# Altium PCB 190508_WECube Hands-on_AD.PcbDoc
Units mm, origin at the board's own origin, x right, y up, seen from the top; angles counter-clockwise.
Board outline 87.3 x 114.68 mm, 5 copper layers (Top, Layer 2, Layer 3, Layer 4, Bottom), stack 1.05 mm thick; 0 components, 0 nets, 41 pads, 0 vias.
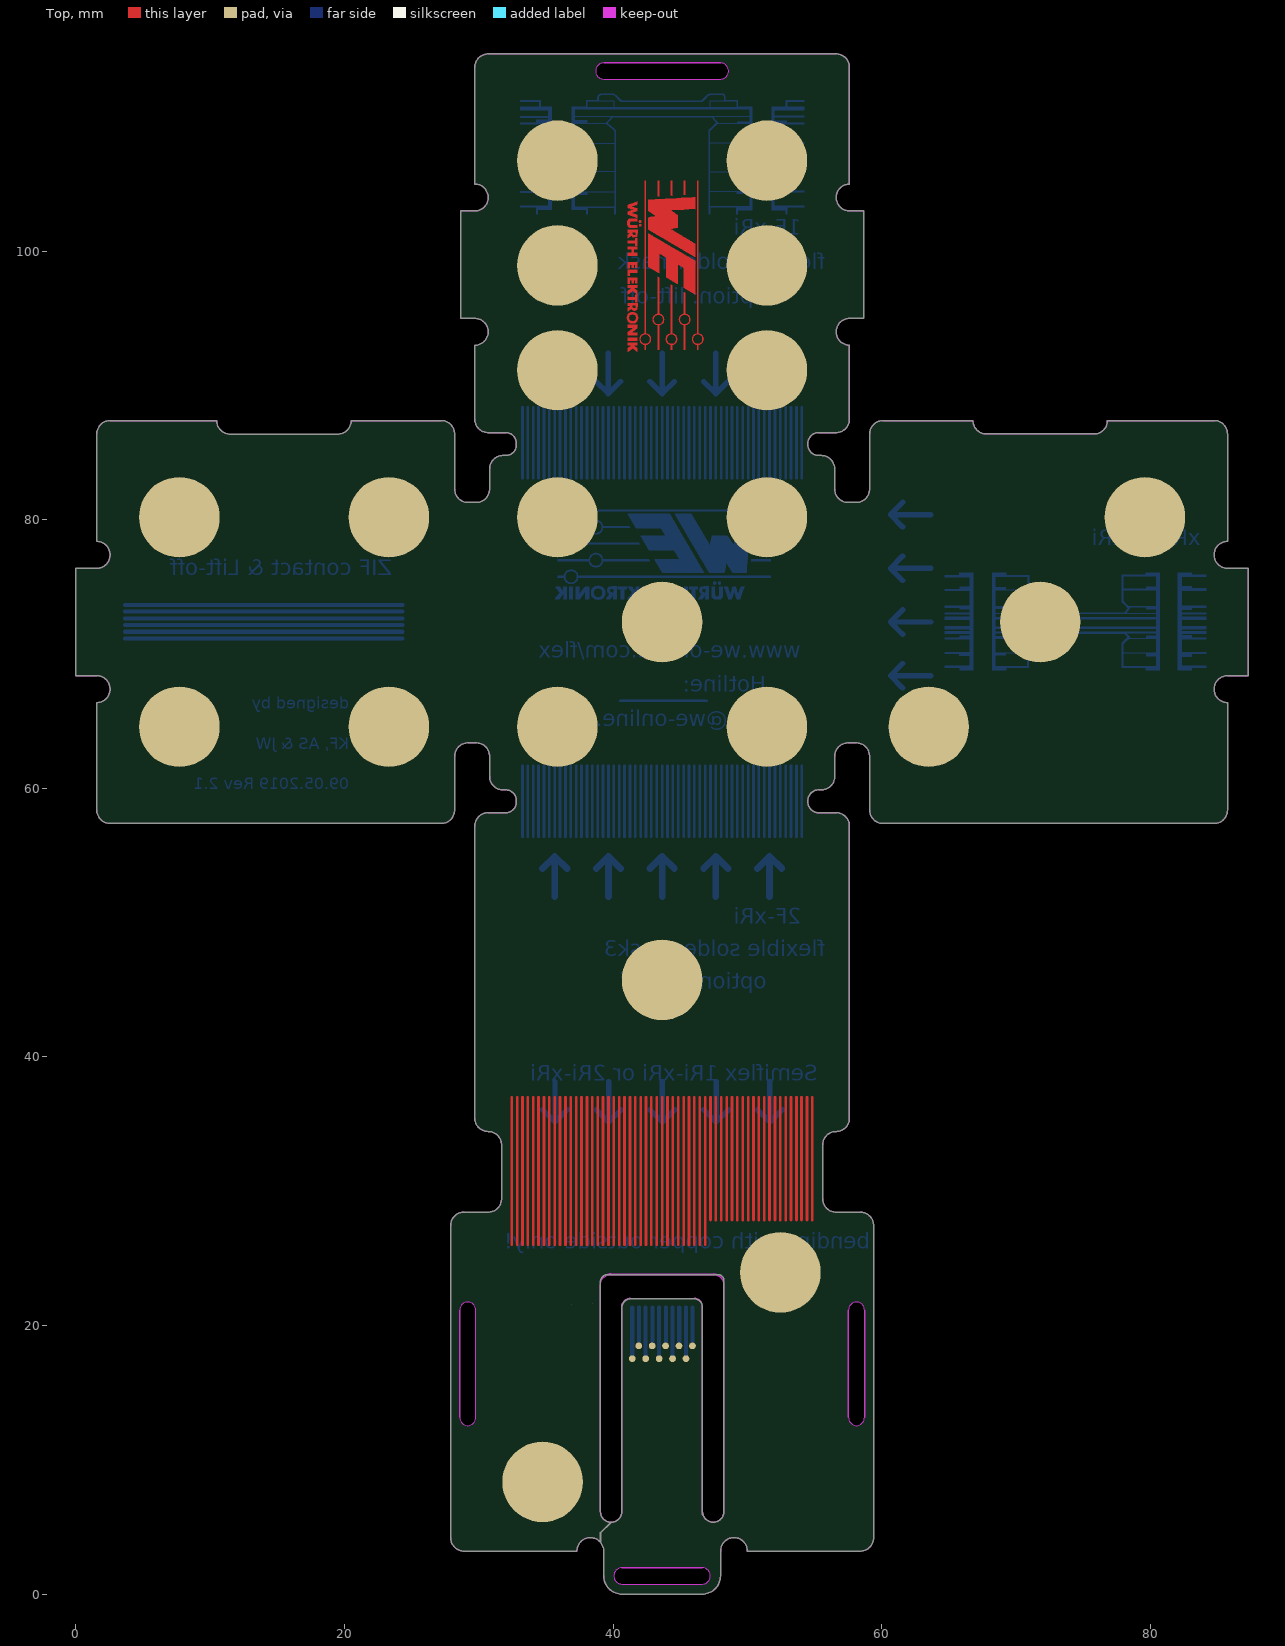
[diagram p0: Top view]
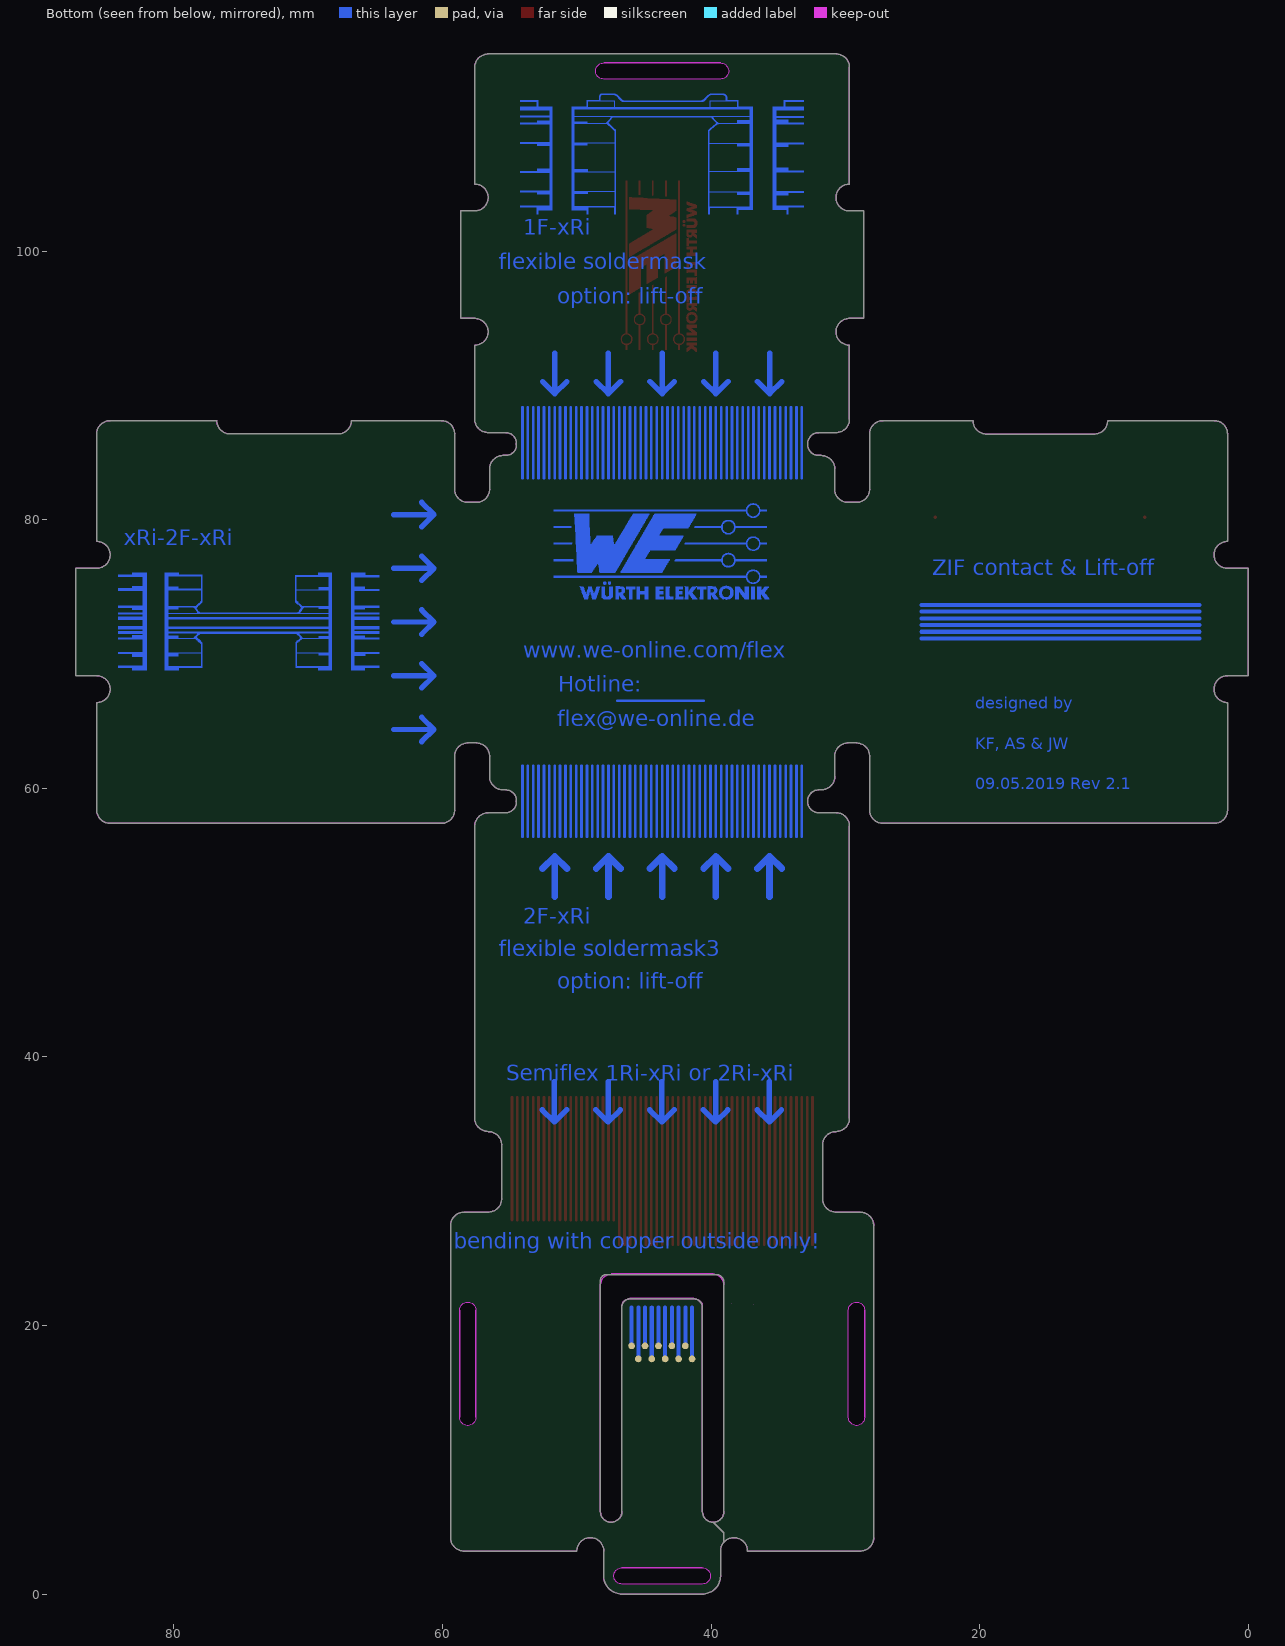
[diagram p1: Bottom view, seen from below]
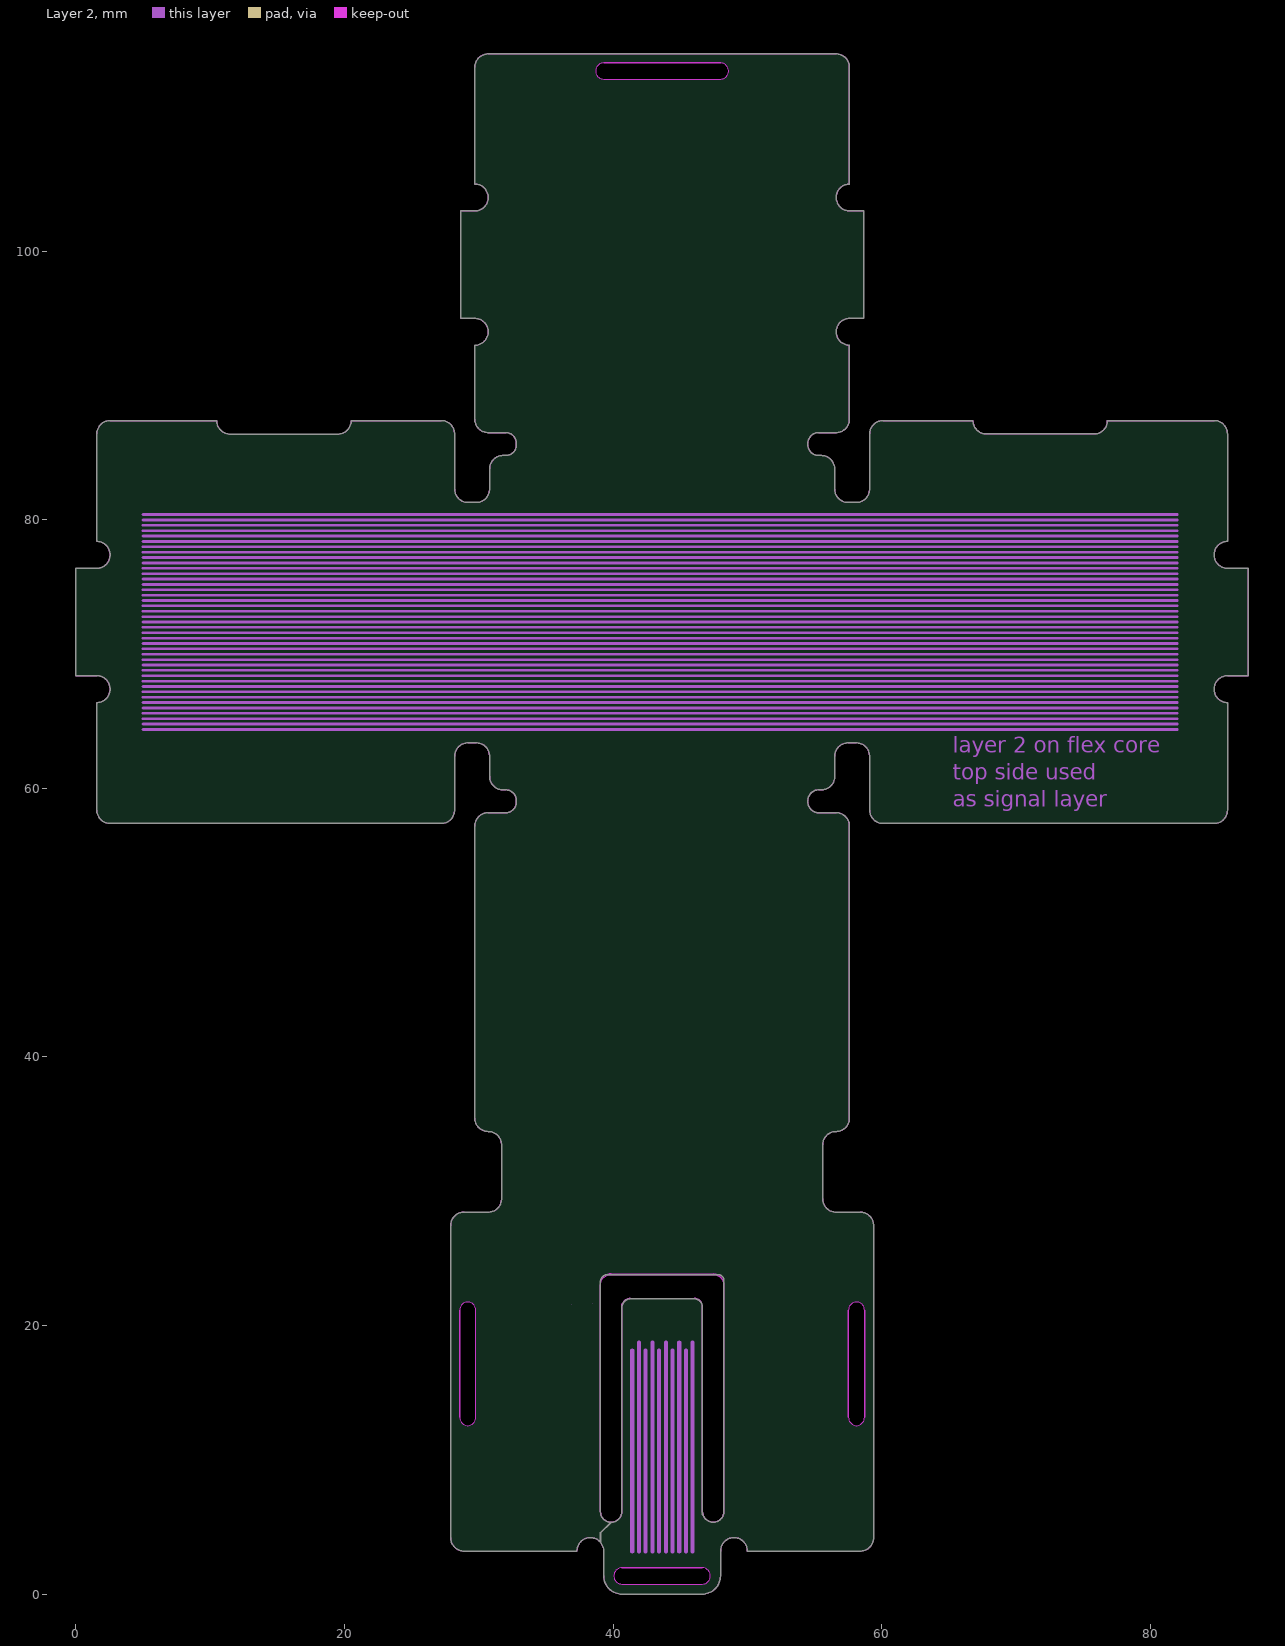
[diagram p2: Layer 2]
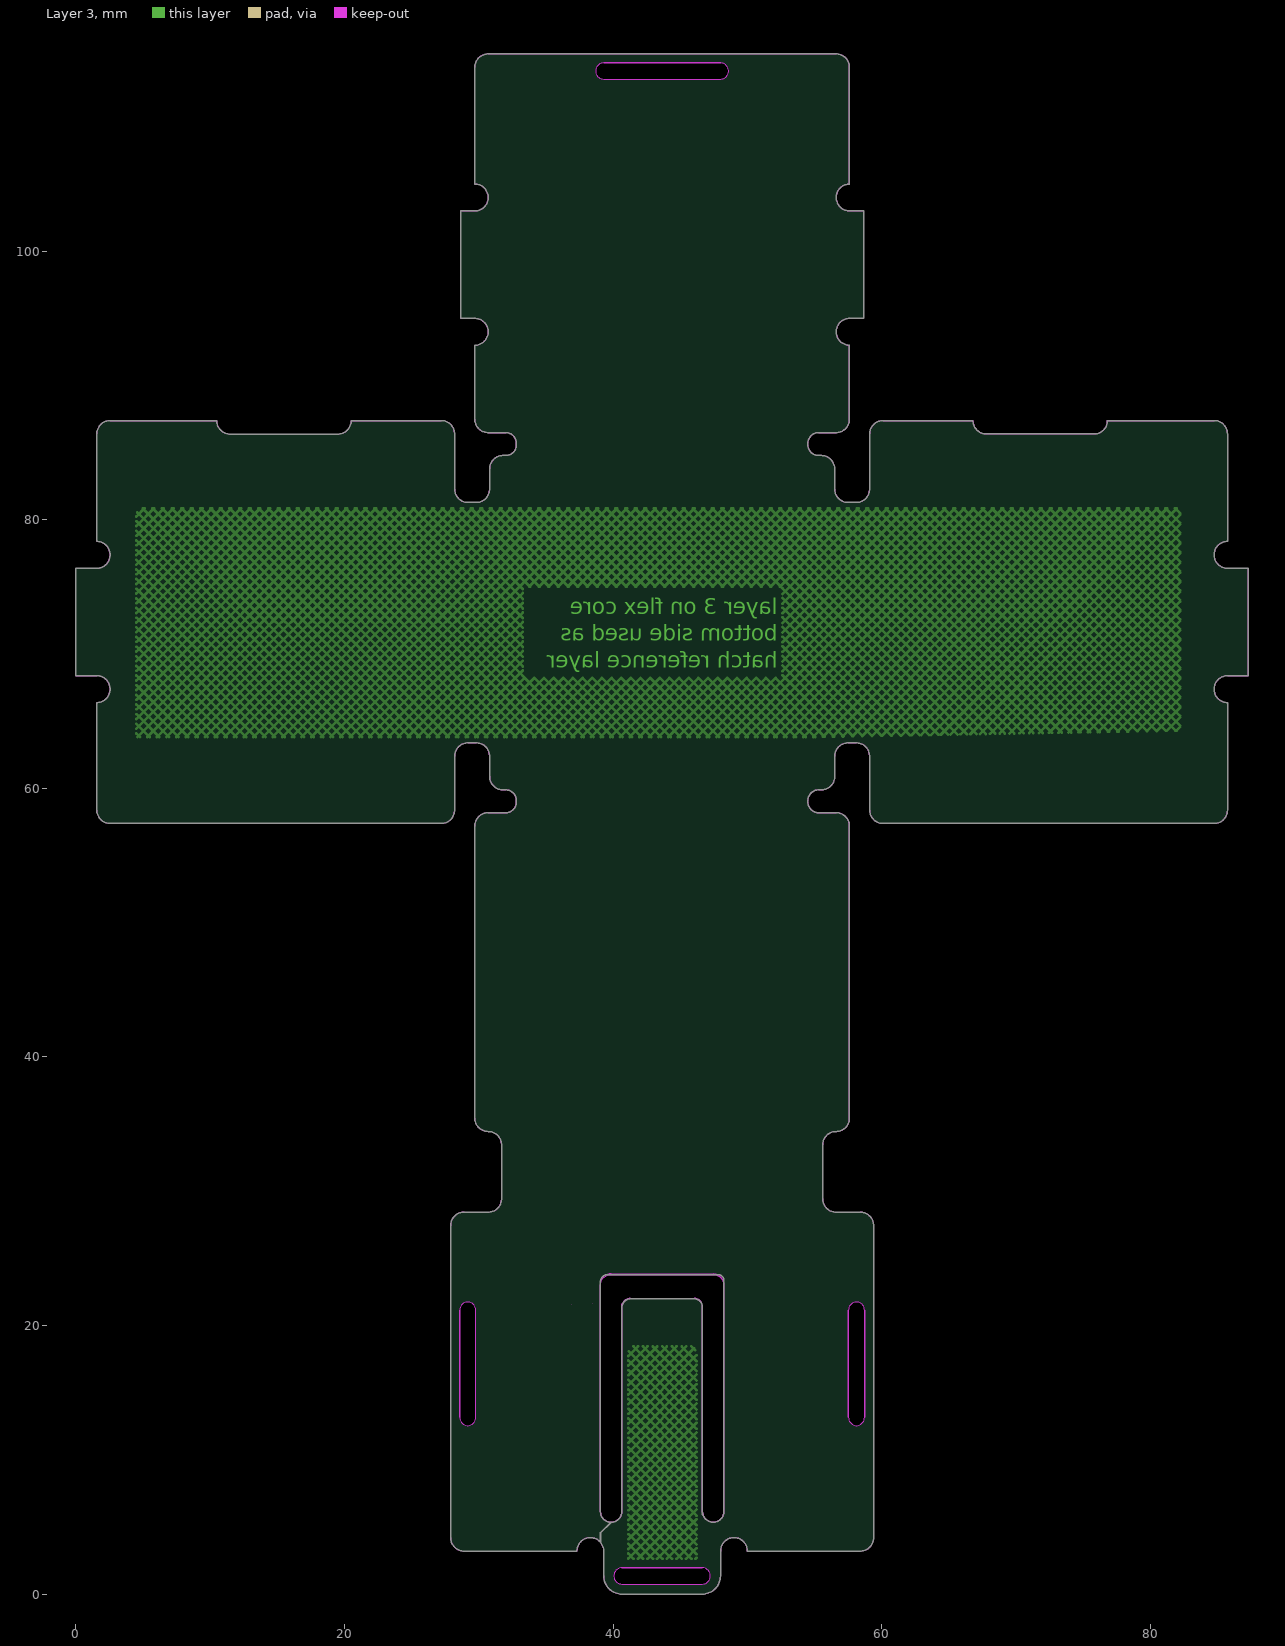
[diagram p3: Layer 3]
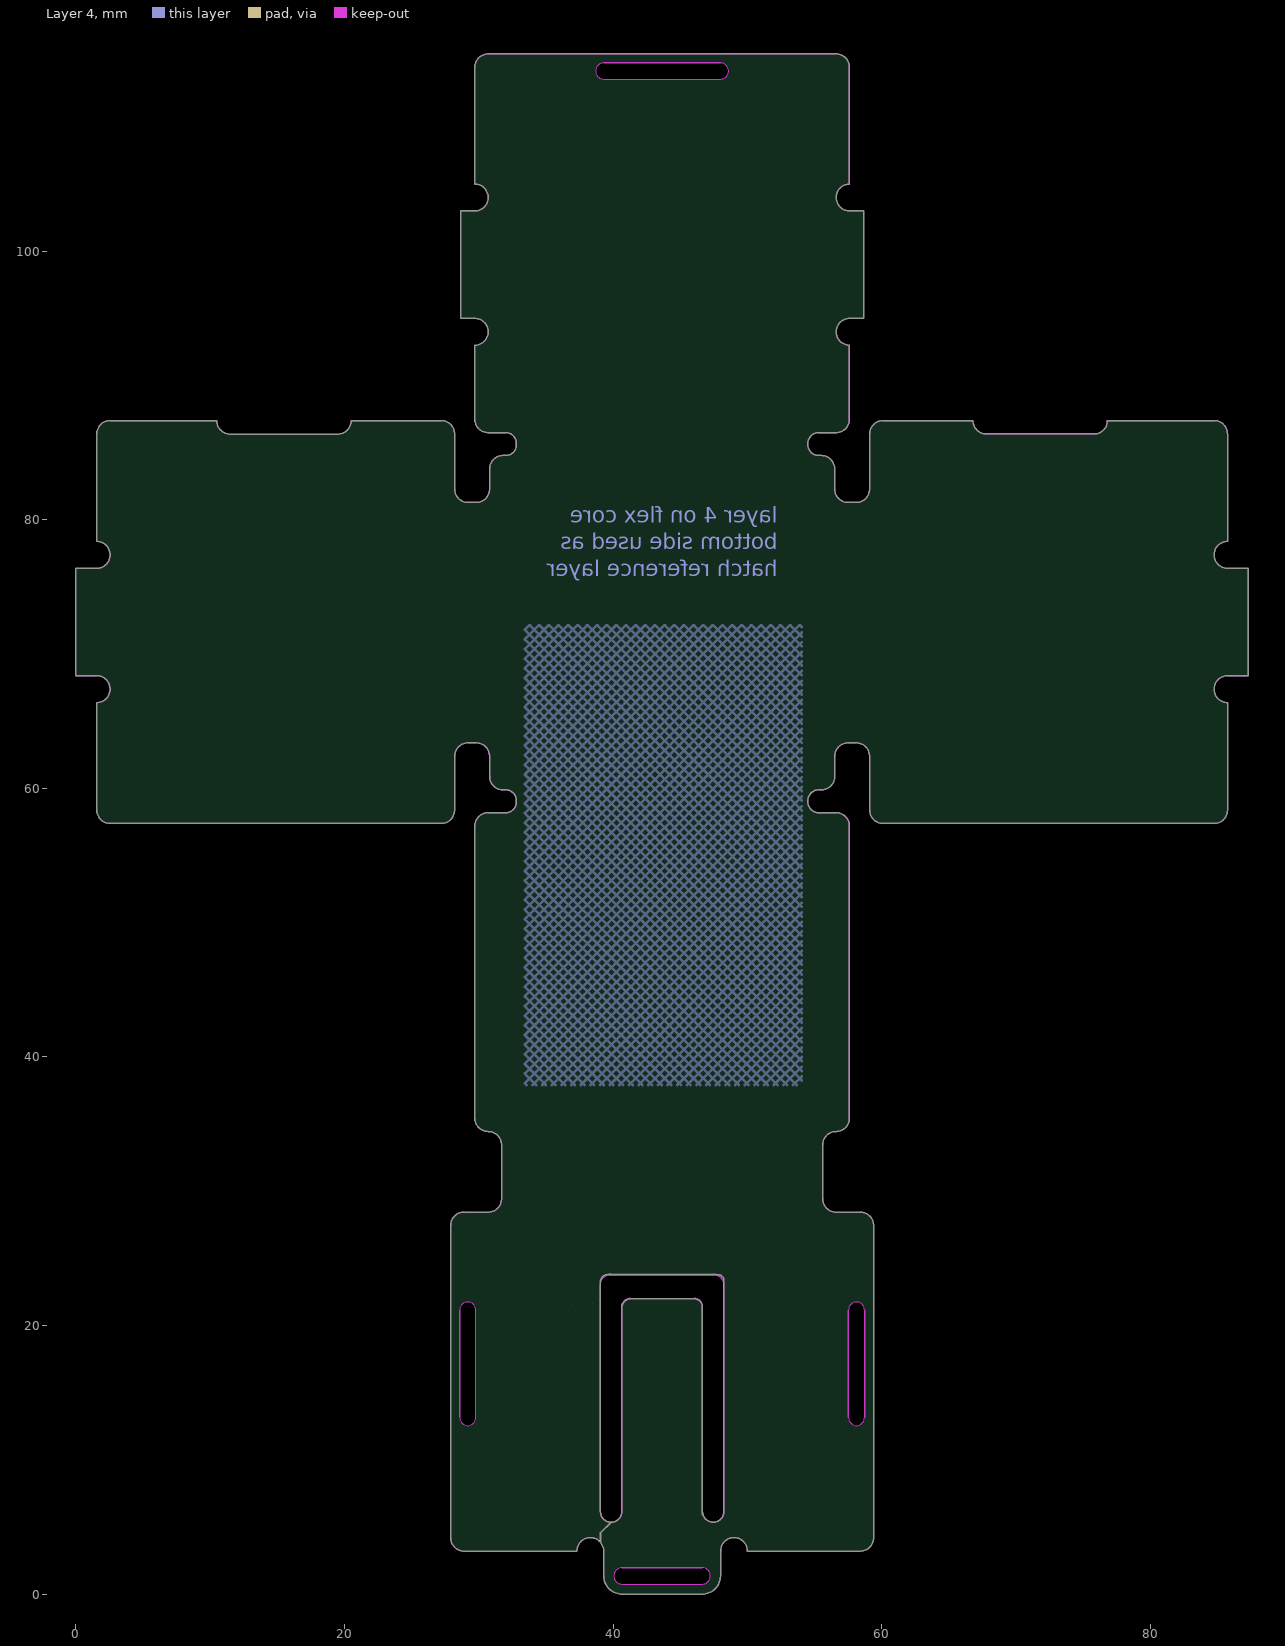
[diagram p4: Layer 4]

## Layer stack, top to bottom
Inner Top Coverlay: solder mask 0.025, Polyimide, Dk 3.6
Inner Top Coverlay: solder mask 0.015, Flexible Solder Resist, Dk 3.4
Inner Top Coverlay: solder mask 0.015, Solder Resist, Dk 3.7
Inner Top Coverlay: solder mask 0.025, Polyimide, Dk 3.6
Top: signal copper 0.04
2x1080: prepreg 0.134, FR4 TG150, Dk 4.2
FR4: core 0.2, Dk 4.2
106 LowFlow: prepreg 0.095, FR4 PP TG150, Dk 4.2
Layer 2: signal copper 0.017
Polyimide 18-50-18: core 0.05, Polyimide adhesiveless, Dk 3.6
Layer 3: signal copper 0.017
106 LowFlow: prepreg 0.095, FR4 PP TG150, Dk 4.9
FR4: core 0.2, FR4 TG150, Dk 4.9
106 LowFlow: prepreg 0.095, FR4 PP TG150, Dk 4.9
Layer 4: signal copper 0.017
Polyimide 18-50-18: core 0.05, Polyimide adhesiveless, Dk 3.6
Bottom: signal copper 0.04
Bottom Coverlay: solder mask 0.015, Polyimide, Dk 3.6
Bottom Coverlay: solder mask 0.015, Solder Resist, Dk 3.7
Bottom Coverlay: solder mask 0.015, Flexible Solder Resist, Dk 3.4
Bottom Coverlay: solder mask 0.025, Polyimide, Dk 3.6

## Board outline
27.9,4.2 ccw(c28.9,4.2) 28.9,3.2 cw(c28.9,3.2) 28.9,3.2 37.3,3.2 cw(c38.3,3.2) 39.054,3.857 39.054,4.569 cw(c39.055,4.569) 39.054,4.569 39.835,5.35 cw(c39.85,6.15) 39.049,6.15 cw(c39.05,6.15) 39.05,6.15 39.05,23.23 cw(c39.61,23.23) 39.61,23.79 47.8,23.79 cw(c47.8,23.34) 48.25,23.34 48.25,6.15 cw(c47.45,6.15) 46.65,6.113 46.65,5.923 cw(c46.65,5.923) 46.65,5.923 46.65,21.387 ccw(c46.057,21.387) 46.057,21.98 41.291,21.98 ccw(c41.291,21.339) 40.65,21.339 40.65,6.15 cw(c40.65,6.15) 40.65,6.15 cw(c39.85,6.15) 39.864,5.35 39.066,4.552 39.066,3.843 cw(c38.3,3.2) 39.3,3.2 39.3,1.35 ccw(c40.65,1.35) 40.65,0 cw(c40.65,0) 40.65,0 46.65,0 ccw(c46.65,1.35) 48,1.35 cw(c48,1.35) 48,1.35 48,3.2 cw(c49,3.2) 50,3.2 58.4,3.2 cw(c58.4,3.2) 58.4,3.2 ccw(c58.4,4.2) 59.4,4.2 59.4,27.44 ccw(c58.4,27.44) 58.4,28.44 56.6,28.44 cw(c56.6,29.44) 55.6,29.44 55.6,33.44 cw(c56.6,33.44) 56.6,34.44 ccw(c56.6,35.44) 57.6,35.44 57.6,57.18 cw(c57.6,57.18) 57.6,57.18 cw(c56.6,57.18) 57.6,57.18 ccw(c56.6,57.18) 56.6,58.18 55.3,58.18 cw(c55.3,58.98) 54.5,58.98 54.5,59.08 cw(c55.3,59.08) 55.3,59.88 55.5,59.88 ccw(c55.5,60.88) 56.5,60.88 56.5,62.38 ccw(c56.5,62.38) 56.5,62.38 cw(c57.5,62.38) 57.5,63.38 58.1,63.38 cw(c58.1,62.38) 59.1,62.38 59.1,58.38 ccw(c59.1,58.38) 59.1,58.38 ccw(c60.1,58.38) 60.1,57.38 84.75,57.38 ccw(c84.75,58.38) 85.75,58.38 cw(c85.75,58.38) 85.75,58.38 85.75,66.38 cw(c85.75,67.38) 85.75,68.38 87.3,68.38 87.3,76.38 85.75,76.38 cw(c85.75,77.38) 85.75,78.38 85.75,86.38 ccw(c84.75,86.38) 84.75,87.38 76.81,87.38 cw(c75.8,87.39) 75.8,86.38 cw(c75.8,87.39) 75.8,86.38 ccw(c75.8,86.38) 75.8,86.38 67.8,86.38 cw(c67.8,86.38) 67.8,86.38 cw(c67.8,87.39) 66.79,87.38 60.1,87.38 cw(c60.1,87.38) 60.1,87.38 cw(c60.1,86.38) 60.1,87.38 ccw(c60.1,86.38) 59.1,86.38 cw(c59.1,86.38) 59.1,86.38 59.1,82.28 cw(c58.1,82.28) 58.1,81.28 57.5,81.28 cw(c57.5,82.28) 56.5,82.28 56.5,83.78 cw(c56.5,83.78) 56.5,83.78 cw(c55.5,83.78) 56.5,83.78 ccw(c55.5,83.78) 55.5,84.78 cw(c55.5,84.78) 55.5,84.78 55.3,84.78 cw(c55.3,85.58) 54.5,85.58 54.5,85.68 cw(c55.3,85.68) 55.3,86.48 56.6,86.48 ccw(c56.6,87.48) 57.6,87.48 57.6,92.99 cw(c57.61,93.99) 57.61,94.99 58.66,94.99 58.66,102.99 57.61,102.99 cw(c57.61,103.99) 57.6,104.99 57.6,113.68 ccw(c56.6,113.68) 56.6,114.68 30.7,114.68 ccw(c30.7,113.68) 29.7,113.68 29.7,104.99 cw(c29.7,103.99) 30.7,103.99 cw(c29.7,103.99) 29.7,102.99 28.65,102.99 28.65,94.99 29.7,94.99 cw(c29.7,93.99) 30.7,93.99 cw(c29.7,93.99) 29.7,92.99 29.7,87.48 ccw(c30.7,87.48) 30.7,86.48 32,86.48 cw(c32,85.68) 32.8,85.68 32.8,85.58 cw(c32,85.58) 32,84.78 31.8,84.78 ccw(c31.8,84.78) 31.8,84.78 ccw(c31.8,83.78) 30.8,83.78 30.8,82.28 cw(c29.8,82.28) 29.8,81.28 29.2,81.28 cw(c29.2,82.28) 28.2,82.28 28.2,86.38 ccw(c27.2,86.38) 27.2,87.38 20.5,87.38 cw(c19.49,87.38) 19.49,86.37 cw(c19.49,87.38) 19.49,86.37 11.49,86.37 cw(c11.49,86.37) 11.49,86.37 cw(c11.49,87.38) 10.48,87.38 2.55,87.38 cw(c2.55,87.38) 2.55,87.38 cw(c2.55,86.38) 2.55,87.38 ccw(c2.55,86.38) 1.55,86.38 1.55,78.38 cw(c1.55,77.38) 2.55,77.38 cw(c1.55,77.38) 1.55,76.38 0,76.38 0,68.38 1.55,68.38 cw(c1.55,67.38) 2.55,67.38 cw(c1.55,67.38) 1.55,66.38 1.55,58.38 cw(c1.55,58.38) 1.55,58.38 cw(c2.55,58.38) 1.55,58.38 ccw(c2.55,58.38) 2.55,57.38 cw(c2.55,57.38) 2.55,57.38 27.2,57.38 ccw(c27.2,58.38) 28.2,58.38 28.2,62.38 cw(c29.2,62.38) 29.2,63.38 29.8,63.38 cw(c29.8,62.38) 30.8,62.38 cw(c30.8,62.38) 30.8,62.38 30.8,60.88 ccw(c31.8,60.88) 31.8,59.88 cw(c31.8,59.88) 31.8,59.88 32,59.88 cw(c32,59.08) 32.8,59.08 32.8,58.98 cw(c32,58.98) 32,58.18 30.7,58.18 ccw(c30.7,57.18) 29.7,57.18 cw(c29.7,57.18) 29.7,57.18 29.7,35.44 ccw(c30.7,35.44) 30.7,34.44 cw(c30.7,33.44) 31.7,33.44 31.7,29.44 cw(c30.7,29.44) 30.7,28.44 28.9,28.44 ccw(c28.9,27.44) 27.9,27.44
cut-out: 39.05,6.15 39.049,22.988 cw(c39.851,22.988) 39.851,23.79 47.446,23.79 cw(c47.446,22.987) 48.25,22.988 48.25,6.15 cw(c47.45,6.15) 46.65,6.15 46.65,21.339 ccw(c46.033,21.363) 46.057,21.98 41.421,21.98 ccw(c41.331,21.298) 40.65,21.387 40.65,6.15 cw(c39.85,6.15)
cut-out: 28.575,13.15 ccw(c29.175,13.15) 29.775,13.15 29.775,21.15 ccw(c29.175,21.15) 28.575,21.15
cut-out: 57.525,13.15 ccw(c58.125,13.15) 58.725,13.15 58.725,21.15 ccw(c58.125,21.15) 57.525,21.15
cut-out: 40.65,0.75 46.65,0.75 ccw(c46.65,1.35) 46.65,1.95 40.65,1.95 ccw(c40.65,1.35)
cut-out: 39.3,112.805 48,112.805 ccw(c48,113.405) 48,114.005 39.3,114.005 ccw(c39.3,113.405)
cut-out: 39.05,6.15
cut-out: 36.88,21.55
cut-out: 38.45,21.67
board region "Layer Stack Region 1": 56.202,28.527 56.31,28.483 56.502,28.444 56.6,28.44 58.4,28.44 58.498,28.44 58.692,28.401 58.873,28.326 59.037,28.216 59.176,28.077 59.286,27.913 59.361,27.732 59.4,27.538 59.4,27.44 59.4,4.2 59.4,4.102 59.361,3.908 59.286,3.727 59.176,3.563 59.037,3.424 58.874,3.314 58.692,3.239 58.498,3.2 58.4,3.2 50,3.2 49.992,3.331 49.924,3.583 49.793,3.809 49.609,3.994 49.383,4.124 49.13,4.192 48.869,4.192 48.617,4.124 48.391,3.994 48.206,3.809 48.076,3.583 48.008,3.331 48,3.2 48,1.35 48,1.217 47.948,0.956 47.846,0.711 47.698,0.49 47.51,0.302 47.289,0.154 47.044,0.052 46.783,0 46.65,0 40.65,0 40.517,0 40.256,0.052 40.011,0.154 39.79,0.302 39.602,0.49 39.454,0.711 39.352,0.956 39.3,1.217 39.3,1.35 39.3,3.2 39.297,3.287 39.266,3.459 39.207,3.623 39.12,3.774 39.066,3.843 39.066,4.552 39.864,5.35 39.941,5.355 40.093,5.387 40.235,5.449 40.247,5.457 47.161,5.404 47.165,5.402 47.365,5.354 47.571,5.359 47.769,5.416 47.946,5.522 48.09,5.669 48.191,5.848 48.244,6.047 48.25,6.15 48.25,23.34 48.242,23.428 48.175,23.59 48.05,23.715 47.888,23.782 47.8,23.79 39.61,23.79 39.501,23.78 39.299,23.696 39.144,23.541 39.06,23.339 39.05,23.23 39.05,6.15 39.053,6.072 39.083,5.92 39.141,5.777 39.227,5.647 39.335,5.537 39.463,5.449 39.606,5.388 39.757,5.355 39.835,5.35 39.054,4.569 39.054,3.857 38.946,3.963 38.689,4.122 38.396,4.196 38.095,4.179 37.812,4.073 37.574,3.888 37.401,3.64 37.311,3.351 37.3,3.2 28.9,3.2 28.802,3.2 28.608,3.239 28.426,3.314 28.263,3.424 28.124,3.563 28.014,3.727 27.939,3.908 27.9,4.102 27.9,4.2 27.9,27.44 27.9,27.538 27.939,27.732 28.014,27.913 28.124,28.077 28.263,28.216 28.427,28.326 28.608,28.401 28.802,28.44 28.9,28.44 30.7,28.44 30.798,28.444 30.99,28.483 31.116,28.535
board region "Layer Stack Region 1": 46.65,16.75 46.65,5.929 46.65,6.113 46.662,6.01 46.724,5.814 46.833,5.64 46.984,5.499 47.161,5.404 40.247,5.457 40.363,5.536 40.472,5.647 40.557,5.776 40.616,5.92 40.646,6.072 40.65,6.15 40.65,16.755
board region "Layer Stack Region 1": 46.65,19.188 46.65,16.75 40.65,16.755 40.65,19.197
board region "Layer Stack Region 1": 56.947,34.502 56.892,34.479 56.698,34.44 56.6,34.44 56.502,34.436 56.31,34.397 56.128,34.322 55.965,34.213 55.827,34.075 55.718,33.912 55.643,33.73 55.604,33.538 55.6,33.44 55.6,29.44 55.604,29.342 55.643,29.15 55.718,28.968 55.827,28.805 55.965,28.667 56.128,28.558 56.202,28.527 31.116,28.535 31.172,28.558 31.335,28.667 31.473,28.805 31.582,28.968 31.657,29.15 31.696,29.342 31.7,29.44 31.7,33.44 31.696,33.538 31.657,33.73 31.582,33.912 31.473,34.075 31.335,34.213 31.172,34.322 30.99,34.397 30.798,34.436 30.7,34.44 30.602,34.44 30.408,34.479 30.339,34.507
board region "Layer Stack Region 1": 55.168,58.194 55.222,58.183 55.3,58.18 56.6,58.18 56.698,58.18 56.892,58.141 57.073,58.066 57.237,57.956 57.376,57.817 57.486,57.654 57.561,57.472 57.6,57.278 57.6,57.18 57.6,35.44 57.6,35.342 57.561,35.148 57.486,34.967 57.376,34.803 57.237,34.664 57.073,34.554 56.947,34.502 30.34,34.507 30.227,34.554 30.063,34.664 29.924,34.803 29.814,34.967 29.739,35.148 29.7,35.342 29.7,35.44 29.7,57.18 29.7,57.278 29.739,57.472 29.814,57.653 29.924,57.817 30.063,57.956 30.227,58.066 30.408,58.141 30.602,58.18 30.7,58.18 32,58.18 32.057,58.182
board region "Layer Stack Region 1": 55.3,59.88 55.222,59.877 55.068,59.846 54.923,59.786 54.792,59.699 54.681,59.588 54.594,59.457 54.534,59.312 54.503,59.158 54.5,59.08 54.5,58.98 54.503,58.902 54.534,58.748 54.594,58.603 54.681,58.472 54.792,58.361 54.923,58.274 55.068,58.214 55.169,58.194 32.056,58.182 32.078,58.183 32.232,58.214 32.377,58.274 32.508,58.361 32.619,58.472 32.706,58.603 32.766,58.748 32.797,58.902 32.8,58.98 32.8,59.08 32.797,59.158 32.766,59.312 32.706,59.457 32.619,59.588 32.508,59.699 32.377,59.786 32.232,59.846 32.078,59.877 32,59.88 31.8,59.88 31.702,59.88 31.609,59.899
board region "Layer Stack Region 1": 28.224,62.578 28.204,62.478 28.2,62.38 28.2,58.38 28.2,58.282 28.161,58.088 28.086,57.907 27.976,57.743 27.837,57.604 27.673,57.494 27.492,57.419 27.298,57.38 27.2,57.38 2.55,57.38 2.452,57.38 2.258,57.419 2.077,57.494 1.913,57.604 1.774,57.743 1.664,57.906 1.589,58.088 1.55,58.282 1.55,58.38 1.55,66.38 1.648,66.384 1.841,66.423 2.022,66.498 2.185,66.607 2.323,66.745 2.432,66.909 2.507,67.09 2.546,67.282 2.55,67.38 2.546,67.478 2.507,67.67 2.432,67.852 2.323,68.015 2.185,68.153 2.022,68.262 1.84,68.337 1.648,68.376 1.55,68.38 0,68.38 0,76.38 1.55,76.38 1.648,76.384 1.84,76.423 2.022,76.498 2.185,76.607 2.323,76.745 2.432,76.908 2.507,77.09 2.546,77.282 2.55,77.38 2.546,77.478 2.507,77.67 2.432,77.851 2.323,78.015 2.185,78.153 2.022,78.262 1.841,78.337 1.648,78.376 1.55,78.38 1.55,86.38 1.55,86.478 1.589,86.672 1.664,86.853 1.774,87.017 1.913,87.156 2.076,87.266 2.258,87.341 2.452,87.38 2.55,87.38 10.48,87.38 10.485,87.281 10.523,87.086 10.599,86.904 10.709,86.739 10.849,86.599 11.014,86.489 11.197,86.413 11.391,86.375 11.49,86.37 19.49,86.37 19.589,86.375 19.783,86.413 19.966,86.489 20.131,86.599 20.271,86.739 20.381,86.904 20.457,87.086 20.495,87.281 20.5,87.38 27.2,87.38 27.298,87.38 27.492,87.341 27.673,87.266 27.837,87.156 27.976,87.017 28.086,86.853 28.161,86.672 28.2,86.478 28.2,86.38 28.2,82.28 28.204,82.182 28.22,82.104
board region "Layer Stack Region 1": 55.538,86.48 55.3,86.48 55.222,86.477 55.068,86.446 54.923,86.386 54.792,86.299 54.681,86.188 54.594,86.057 54.534,85.912 54.503,85.758 54.5,85.68 54.5,85.58 54.503,85.502 54.534,85.348 54.594,85.203 54.681,85.072 54.792,84.961 54.923,84.874 55.068,84.814 55.222,84.783 55.282,84.78 32.08,84.784 32.232,84.814 32.377,84.874 32.508,84.961 32.619,85.072 32.706,85.203 32.766,85.348 32.797,85.502 32.8,85.58 32.8,85.68 32.797,85.758 32.766,85.912 32.706,86.057 32.619,86.188 32.508,86.299 32.377,86.386 32.232,86.446 32.078,86.477 32,86.48 30.7,86.48 30.602,86.48 30.413,86.518
board region "Layer Stack Region 1": 30.413,86.518 30.408,86.519 30.227,86.594 30.063,86.704 29.924,86.843 29.814,87.007 29.739,87.188 29.7,87.382 29.7,87.48 29.7,92.99 29.798,92.994 29.991,93.033 30.172,93.108 30.335,93.217 30.473,93.355 30.582,93.519 30.657,93.7 30.696,93.892 30.7,93.99 30.696,94.088 30.657,94.28 30.582,94.462 30.473,94.625 30.335,94.763 30.172,94.872 29.99,94.947 29.798,94.986 29.7,94.99 28.65,94.99 28.65,102.99 29.7,102.99 29.798,102.994 29.99,103.033 30.172,103.108 30.335,103.217 30.473,103.355 30.582,103.518 30.657,103.7 30.696,103.892 30.7,103.99 30.696,104.088 30.657,104.28 30.582,104.461 30.473,104.625 30.335,104.763 30.172,104.872 29.991,104.947 29.798,104.986 29.7,104.99 29.7,113.68 29.7,113.778 29.739,113.972 29.814,114.153 29.924,114.317 30.063,114.456 30.227,114.566 30.408,114.641 30.602,114.68 30.7,114.68 56.6,114.68 56.698,114.68 56.892,114.641 57.073,114.566 57.237,114.456 57.376,114.317 57.486,114.153 57.561,113.972 57.6,113.778 57.6,113.68 57.6,104.99 57.47,104.981 57.219,104.911 56.994,104.779 56.812,104.593 56.683,104.367 56.617,104.115 56.619,103.855 56.687,103.604 56.818,103.379 57.003,103.195 57.228,103.065 57.48,102.998 57.61,102.99 58.66,102.99 58.66,94.99 57.61,94.99 57.48,94.982 57.228,94.915 57.003,94.785 56.818,94.601 56.687,94.376 56.619,94.125 56.617,93.865 56.683,93.613 56.812,93.387 56.994,93.201 57.219,93.069 57.47,92.999 57.6,92.99 57.6,87.48 57.6,87.382 57.561,87.188 57.486,87.007 57.376,86.843 57.237,86.704 57.073,86.594 56.892,86.519 56.698,86.48 56.6,86.48 55.525,86.48
board region "Layer Stack Region 1": 30.757,62.672 30.682,62.852 30.573,63.015 30.435,63.153 30.272,63.262 30.09,63.337 29.898,63.376 29.8,63.38 29.2,63.38 29.102,63.376 28.91,63.337 28.728,63.262 28.565,63.153 28.427,63.015 28.318,62.852 28.243,62.67 28.224,62.578 28.22,82.104 28.243,81.99 28.318,81.808 28.427,81.645 28.565,81.507 28.728,81.398 28.91,81.323 29.102,81.284 29.2,81.28 29.8,81.28 29.898,81.284 30.09,81.323 30.272,81.398 30.435,81.507 30.573,81.645 30.682,81.808 30.757,81.99 30.775,82.08
board region "Layer Stack Region 1": 56.536,62.636 56.504,62.478 56.5,62.38 56.5,60.88 56.5,60.782 56.461,60.588 56.386,60.407 56.276,60.243 56.137,60.104 55.973,59.994 55.792,59.919 55.598,59.88 55.5,59.88 55.303,59.88 31.609,59.899 31.508,59.919 31.327,59.994 31.163,60.104 31.024,60.243 30.914,60.407 30.839,60.588 30.8,60.782 30.8,60.88 30.8,62.38 30.796,62.478 30.757,62.67 30.757,62.672 30.775,82.08 30.796,82.182 30.8,82.28 30.8,83.78 30.8,83.878 30.839,84.072 30.914,84.253 31.024,84.417 31.163,84.556 31.327,84.666 31.508,84.741 31.702,84.78 31.8,84.78 32,84.78 32.078,84.783 32.08,84.784 55.282,84.78 55.3,84.78 55.5,84.78 55.598,84.78 55.792,84.741 55.973,84.666 56.137,84.556 56.276,84.417 56.386,84.254 56.461,84.072 56.5,83.878 56.5,83.78 56.5,82.28 56.502,82.226
board region "Layer Stack Region 1": 59.057,81.988 59.057,81.99 59.096,82.182 59.1,82.28 59.1,86.38 59.1,86.478 59.139,86.672 59.214,86.853 59.324,87.017 59.463,87.156 59.626,87.266 59.808,87.341 60.002,87.38 60.1,87.38 66.79,87.38 66.796,87.281 66.836,87.089 66.912,86.907 67.023,86.745 67.162,86.606 67.326,86.497 67.508,86.423 67.701,86.384 67.8,86.38 75.8,86.38 75.899,86.384 76.092,86.423 76.274,86.497 76.438,86.606 76.577,86.745 76.688,86.907 76.764,87.089 76.804,87.281 76.81,87.38 84.75,87.38 84.848,87.38 85.042,87.341 85.223,87.266 85.387,87.156 85.526,87.017 85.636,86.853 85.711,86.672 85.75,86.478 85.75,86.38 85.75,78.38 85.619,78.372 85.367,78.304 85.141,78.173 84.956,77.989 84.826,77.763 84.758,77.51 84.758,77.249 84.826,76.997 84.956,76.771 85.141,76.586 85.367,76.456 85.619,76.388 85.75,76.38 87.3,76.38 87.3,68.38 85.75,68.38 85.619,68.372 85.367,68.304 85.141,68.174 84.956,67.989 84.826,67.763 84.758,67.511 84.758,67.25 84.826,66.997 84.956,66.771 85.141,66.587 85.367,66.456 85.619,66.388 85.75,66.38 85.75,58.38 85.75,58.282 85.711,58.088 85.636,57.906 85.526,57.743 85.387,57.604 85.223,57.494 85.042,57.419 84.848,57.38 84.75,57.38 60.1,57.38 60.002,57.38 59.808,57.419 59.627,57.494 59.463,57.604 59.324,57.743 59.214,57.907 59.139,58.088 59.1,58.282 59.1,58.38 59.1,62.38 59.096,62.478 59.057,62.67 59.057,62.672
board region "Layer Stack Region 1": 56.502,82.226 56.504,82.182 56.543,81.99 56.618,81.808 56.727,81.645 56.865,81.507 57.028,81.398 57.21,81.323 57.402,81.284 57.5,81.28 58.1,81.28 58.198,81.284 58.39,81.323 58.572,81.398 58.735,81.507 58.873,81.645 58.982,81.808 59.057,81.988 59.057,62.672 58.982,62.852 58.873,63.015 58.735,63.153 58.572,63.262 58.39,63.337 58.198,63.376 58.1,63.38 57.5,63.38 57.402,63.376 57.21,63.337 57.028,63.262 56.865,63.153 56.727,63.015 56.618,62.852 56.543,62.67 56.536,62.636
board region "Layer Stack Region 1": 40.65,19.197 40.65,21.339 40.65,21.467 40.748,21.702 40.928,21.882 41.164,21.98 41.291,21.98 46.057,21.98 46.175,21.98 46.393,21.89 46.559,21.723 46.65,21.505 46.65,21.387 46.65,19.188

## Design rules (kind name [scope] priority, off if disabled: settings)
BoardOutlineClearance [All] p1: gap=0.254 ignorepadtopadclearanceinfootprint=FALSE except(0: Arc-SplitContinuation Track-SplitContinuation SMDPad-SplitContinuation THPad-SplitContinuation Via-SplitContinuation Fill-SplitContinuation Poly-SplitContinuation Region-SplitContinuation Text-SplitContinuation; 0.3: SMDPad-SplitBarrior; 1.5: THPad-SplitBarrior Via-SplitBarrior)
Clearance [All] p1: gap=0.254 ignorepadtopadclearanceinfootprint=FALSE except(0: Arc-Hole Track-Hole SMDPad-Hole THPad-Hole Via-Hole Fill-Hole Poly-Hole Region-Hole Text-Hole)
PolygonConnect [All] p1: connectstyle=Relief reliefconductorwidth=0.254 reliefentries=4 polygonreliefangle="90 Angle" airgapwidth=0.254
RoutingVias [All] p1: holewidth=0.711 width=1.27 viastyle="Through Hole" minholewidth=0.711 minwidth=1.27 maxholewidth=0.711 maxwidth=1.27
SolderMaskExpansion [All] p1: expansion=0.102
Width [All] p1: maxlimit=0.254 minlimit=0.254 preferedwidth=0.254
30 further rules are at their usual default settings.

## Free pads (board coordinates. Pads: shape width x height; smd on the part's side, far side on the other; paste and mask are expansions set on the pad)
  round 6 smd: 1(7.7,64.58) 1(7.7,80.18) 1(23.3,64.58) 1(23.3,80.18) 1(34.75,8.35) 1(35.85,64.58) 1(35.85,80.18) 1(35.85,91.13) 1(35.85,98.93) 1(35.85,106.73) 1(43.65,45.73) 1(43.65,72.38) 1(51.45,64.58) 1(51.45,80.18) 1(51.45,91.13) 1(51.45,98.93) 1(51.45,106.73) 1(52.45,23.95) 1(63.5,64.58) 1(71.8,72.38) 1(79.6,80.18)
  round 0.5 smd mask+0: 2(41.425,17.53) 3(42.425,17.53) 4(43.425,17.53) 5(44.425,17.53) 6(45.425,17.53) 7(41.905,18.48) 8(42.905,18.48) 9(43.905,18.48) 10(44.905,18.48) 11(45.905,18.48)
  round 0.5 smd far side mask+0: 2(41.425,17.51) 3(42.425,17.51) 4(43.425,17.51) 5(44.425,17.51) 6(45.425,17.51) 7(41.925,18.48) 8(42.925,18.48) 9(43.925,18.48) 10(44.925,18.48) 11(45.925,18.48)

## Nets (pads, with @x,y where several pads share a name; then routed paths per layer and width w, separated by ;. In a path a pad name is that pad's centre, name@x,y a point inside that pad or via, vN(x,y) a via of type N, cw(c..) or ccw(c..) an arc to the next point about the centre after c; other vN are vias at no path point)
copper on no net: | length 4778.1
  Top w0.2: 32.45,26 32.45,37 ; 32.85,26 32.85,37 ; 33.25,26 33.25,37 ; 33.65,26 33.65,37 ; 34.05,26 34.05,37 ; 34.45,26 34.45,37 ; 34.85,26 34.85,37 ; 35.25,26 35.25,37 ; 35.65,26 35.65,37 ; 36.05,26 36.05,37 ; 36.45,26 36.45,37 ; 36.85,26 36.85,37 ; 37.25,26 37.25,37 ; 37.65,26 37.65,37 ; 38.05,26 38.05,37 ; 38.45,26 38.45,37 ; 38.85,26 38.85,37 ; 39.25,26 39.25,37 ; 39.65,26 39.65,37 ; 40.05,26 40.05,37 ; 40.45,26 40.45,37 ; 40.85,26 40.85,37 ; 41.25,26 41.25,37 ; 41.65,26 41.65,37 ; 42.05,26 42.05,37 ; 42.45,26 42.45,37 ; 42.85,26 42.85,37 ; 43.25,26 43.25,37 ; 43.65,26 43.65,37 ; 44.05,26 44.05,37 ; 44.45,26 44.45,37 ; 44.85,26 44.85,37 ; 45.25,26 45.25,37 ; 45.65,26 45.65,37 ; 46.05,26 46.05,37 ; 46.45,26 46.45,37 ; 46.85,26 46.85,37 ; 47.25,27.85 47.25,37 ; 47.65,27.85 47.65,37 ; 48.05,27.85 48.05,37 ; 48.45,27.85 48.45,37 ; 48.85,27.85 48.85,37 ; 49.25,27.85 49.25,37 ; 49.65,27.85 49.65,37 ; 50.05,27.85 50.05,37 ; 50.45,27.85 50.45,37 ; 50.85,27.85 50.85,37 ; 51.25,27.85 51.25,37 ; 51.65,27.85 51.65,37 ; 52.05,27.85 52.05,37 ; 52.45,27.85 52.45,37 ; 52.85,27.85 52.85,37 ; 53.25,27.85 53.25,37 ; 53.65,27.85 53.65,37 ; 54.03,27.85 54.03,37 ; 54.43,27.85 54.43,37 ; 54.83,27.85 54.83,37
  Layer 2 w0.2: 5,64.38 82,64.38 ; 5,64.78 82,64.78 ; 5,65.18 82,65.18 ; 5,65.58 82,65.58 ; 5,65.98 82,65.98 ; 5,66.38 82,66.38 ; 5,66.78 82,66.78 ; 5,67.18 82,67.18 ; 5,67.58 82,67.58 ; 5,67.98 82,67.98 ; 5,68.38 82,68.38 ; 5,68.78 82,68.78 ; 5,69.18 82,69.18 ; 5,69.58 82,69.58 ; 5,69.98 82,69.98 ; 5,70.38 82,70.38 ; 5,70.78 82,70.78 ; 5,71.18 82,71.18 ; 5,71.58 82,71.58 ; 5,71.98 82,71.98 ; 5,72.38 82,72.38 ; 5,72.78 82,72.78 ; 5,73.18 82,73.18 ; 5,73.58 82,73.58 ; 5,73.98 82,73.98 ; 5,74.38 82,74.38 ; 5,74.78 82,74.78 ; 5,75.18 82,75.18 ; 5,75.58 82,75.58 ; 5,75.98 82,75.98 ; 5,76.38 82,76.38 ; 5,76.78 82,76.78 ; 5,77.18 82,77.18 ; 5,77.58 82,77.58 ; 5,77.98 82,77.98 ; 5,78.38 82,78.38 ; 5,78.78 82,78.78 ; 5,79.18 82,79.18 ; 5,79.58 82,79.58 ; 5,79.98 82,79.98 ; 5,80.38 82,80.38
  Layer 2 w0.3: 41.425,3.167 41.425,18.127 ; 41.925,3.167 41.925,18.727 ; 42.425,3.167 42.425,18.127 ; 42.925,3.167 42.925,18.727 ; 43.425,3.167 43.425,18.127 ; 43.925,3.167 43.925,18.727 ; 44.425,3.167 44.425,18.127 ; 44.925,3.167 44.925,18.727 ; 45.425,3.167 45.425,18.127 ; 45.925,3.167 45.925,18.727
  Bottom w0.02: 41.2,66.54 ccw(c41.22,66.54) 41.22,66.52
  Bottom w0.2: 33.25,56.38 33.25,61.68 ; 33.25,83.08 33.25,88.38 ; 33.65,56.38 33.65,61.68 ; 33.65,83.08 33.65,88.38 ; 34.05,56.38 34.05,61.68 ; 34.05,83.08 34.05,88.38 ; 34.45,56.38 34.45,61.68 ; 34.45,83.08 34.45,88.38 ; 34.85,56.38 34.85,61.68 ; 34.85,83.08 34.85,88.38 ; 35.25,56.38 35.25,61.68 ; 35.25,83.08 35.25,88.38 ; 35.65,56.38 35.65,61.68 ; 35.65,83.08 35.65,88.38 ; 36.05,56.38 36.05,61.68 ; 36.05,83.08 36.05,88.38 ; 36.45,56.38 36.45,61.68 ; 36.45,83.08 36.45,88.38 ; 36.85,56.38 36.85,61.68 ; 36.85,83.08 36.85,88.38 ; 37.25,56.38 37.25,61.68 ; 37.25,83.08 37.25,88.38 ; 37.65,56.38 37.65,61.68 ; 37.65,83.08 37.65,88.38 ; 38.05,56.38 38.05,61.68 ; 38.05,83.08 38.05,88.38 ; 38.45,56.38 38.45,61.68 ; 38.45,83.08 38.45,88.38 ; 38.85,56.38 38.85,61.68 ; 38.85,83.08 38.85,88.38 ; 39.25,56.38 39.25,61.68 ; 39.25,83.08 39.25,88.38 ; 39.65,56.38 39.65,61.68 ; 39.65,83.08 39.65,88.38 ; 40.05,56.38 40.05,61.68 ; 40.05,83.08 40.05,88.38 ; 40.45,56.38 40.45,61.68 ; 40.45,83.08 40.45,88.38 ; 40.55,66.52 46.97,66.52 ; 40.85,56.38 40.85,61.68 ; 40.85,83.08 40.85,88.38 ; 41.25,56.38 41.25,61.68 ; 41.25,83.08 41.25,88.38 ; 41.65,56.38 41.65,61.68 ; 41.65,83.08 41.65,88.38 ; 42.05,56.38 42.05,61.68 ; 42.05,83.08 42.05,88.38 ; 42.45,56.38 42.45,61.68 ; 42.45,83.08 42.45,88.38 ; 42.85,56.38 42.85,61.68 ; 42.85,83.08 42.85,88.38 ; 43.25,56.38 43.25,61.68 ; 43.25,83.08 43.25,88.38 ; 43.65,56.38 43.65,61.68 ; 43.65,83.08 43.65,88.38 ; 44.05,56.38 44.05,61.68 ; 44.05,83.08 44.05,88.38 ; 44.45,56.38 44.45,61.68 ; 44.45,83.08 44.45,88.38 ; 44.85,56.38 44.85,61.68 ; 44.85,83.08 44.85,88.38 ; 45.25,56.38 45.25,61.68 ; 45.25,83.08 45.25,88.38 ; 45.65,56.38 45.65,61.68 ; 45.65,83.08 45.65,88.38 ; 46.05,56.38 46.05,61.68 ; 46.05,83.08 46.05,88.38 ; 46.45,56.38 46.45,61.68 ; 46.45,83.08 46.45,88.38 ; 46.85,56.38 46.85,61.68 ; 46.85,83.08 46.85,88.38 ; 47.25,56.38 47.25,61.68 ; 47.25,83.08 47.25,88.38 ; 47.65,56.38 47.65,61.68 ; 47.65,83.08 47.65,88.38 ; 48.05,56.38 48.05,61.68 ; 48.05,83.08 48.05,88.38 ; 48.45,56.38 48.45,61.68 ; 48.45,83.08 48.45,88.38 ; 48.85,56.38 48.85,61.68 ; 48.85,83.08 48.85,88.38 ; 49.25,56.38 49.25,61.68 ; 49.25,83.08 49.25,88.38 ; 49.65,56.38 49.65,61.68 ; 49.65,83.08 49.65,88.38 ; 50.05,56.38 50.05,61.68 ; 50.05,83.08 50.05,88.38 ; 50.45,56.38 50.45,61.68 ; 50.45,83.08 50.45,88.38 ; 50.85,56.38 50.85,61.68 ; 50.85,83.08 50.85,88.38 ; 51.25,56.38 51.25,61.68 ; 51.25,83.08 51.25,88.38 ; 51.65,56.38 51.65,61.68 ; 51.65,83.08 51.65,88.38 ; 52.05,56.38 52.05,61.68 ; 52.05,83.08 52.05,88.38 ; 52.45,56.38 52.45,61.68 ; 52.45,83.08 52.45,88.38 ; 52.85,56.38 52.85,61.68 ; 52.85,83.08 52.85,88.38 ; 53.25,56.38 53.25,61.68 ; 53.25,83.08 53.25,88.38 ; 53.65,56.38 53.65,61.68 ; 53.65,83.08 53.65,88.38 ; 54.05,56.38 54.05,61.68 ; 54.05,83.08 54.05,88.38
  Bottom w0.3: 3.65,71.155 24.33,71.155 ; 3.65,71.655 24.33,71.655 ; 3.65,72.655 24.33,72.655 ; 3.65,73.155 24.33,73.155 ; 41.425,17.51 41.425,21.327 ; 41.925,18.48 41.925,21.327 ; 42.425,17.51 42.425,21.327 ; 42.925,18.48 42.925,21.327 ; 43.425,17.51 43.425,21.327 ; 43.925,18.48 43.925,21.327 ; 44.425,17.51 44.425,21.327 ; 44.925,18.5 44.925,21.327 ; 45.425,17.51 45.425,21.327 ; 45.925,18.48 45.925,21.327 ; 3.65,72.155 24.33,72.155 3.65,72.155 ; 3.65,73.655 24.33,73.655 3.65,73.655
  Bottom w0.4: 34.74,90.29 35.65,89.38 ; 34.76,36.06 35.67,35.15 ; 35.65,92.38 35.65,89.38 ; 35.67,38.15 35.67,35.15 ; 36.56,90.29 35.65,89.38 ; 36.58,36.06 35.67,35.15 ; 38.74,90.29 39.65,89.38 ; 38.76,36.06 39.67,35.15 ; 39.65,92.38 39.65,89.38 ; 39.67,38.15 39.67,35.15 ; 40.56,90.29 39.65,89.38 ; 40.58,36.06 39.67,35.15 ; 42.74,90.29 43.65,89.38 ; 42.76,36.06 43.67,35.15 ; 43.65,92.38 43.65,89.38 ; 43.67,38.15 43.67,35.15 ; 44.56,90.29 43.65,89.38 ; 44.58,36.06 43.67,35.15 ; 46.74,90.29 47.65,89.38 ; 46.76,36.06 47.67,35.15 ; 47.65,92.38 47.65,89.38 ; 47.67,38.15 47.67,35.15 ; 48.56,90.29 47.65,89.38 ; 48.58,36.06 47.67,35.15 ; 50.74,90.29 51.65,89.38 ; 50.76,36.06 51.67,35.15 ; 51.65,92.38 51.65,89.38 ; 51.67,38.15 51.67,35.15 ; 52.56,90.29 51.65,89.38 ; 52.58,36.06 51.67,35.15 ; 61.56,63.47 60.65,64.38 ; 61.56,65.29 60.65,64.38 ; 61.56,67.47 60.65,68.38 ; 61.56,69.29 60.65,68.38 ; 61.56,71.47 60.65,72.38 ; 61.56,73.29 60.65,72.38 ; 61.56,75.47 60.65,76.38 ; 61.56,77.29 60.65,76.38 ; 61.56,79.47 60.65,80.38 ; 61.56,81.29 60.65,80.38 ; 63.65,64.38 60.65,64.38 ; 63.65,68.38 60.65,68.38 ; 63.65,72.38 60.65,72.38 ; 63.65,76.38 60.65,76.38 ; 63.65,80.38 60.65,80.38
  Bottom w0.5: 34.74,54.02 35.65,54.93 ; 35.65,51.93 35.65,54.93 ; 36.56,54.02 35.65,54.93 ; 38.74,54.02 39.65,54.93 ; 39.65,51.93 39.65,54.93 ; 40.56,54.02 39.65,54.93 ; 42.74,54.02 43.65,54.93 ; 43.65,51.93 43.65,54.93 ; 44.56,54.02 43.65,54.93 ; 46.74,54.02 47.65,54.93 ; 47.65,51.93 47.65,54.93 ; 48.56,54.02 47.65,54.93 ; 50.74,54.02 51.65,54.93 ; 51.65,51.93 51.65,54.93 ; 52.56,54.02 51.65,54.93

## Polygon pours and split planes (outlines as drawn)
no net on Layer 3 "Reference plane to layer L2" (hatched 45Degree grid 0.508 track 0.203, pour order 18): 82.21,64.295 54.08,63.81 4.5,63.81 4.5,80.45 4.899,80.85 82.21,80.85
no net on Layer 3 "Reference plane to layer L2" (hatched 45Degree grid 0.508 track 0.203, pour order 22): 46.215,18.447 46.214,2.627 41.13,2.627 41.13,18.447
no net on Layer 3 "l3-No Net" (hatched Horizontal grid 0.508 track 0.203, pour order 14): 26.68,80.88
no net on Layer 3 "l3-No Net 1" (hatched Horizontal grid 0.508 track 0.203, pour order 12): 26.68,80.88
no net on Layer 3 "l3-No Net 2" (hatched Horizontal grid 0.508 track 0.203, pour order 10): 32.55,80.79
no net on Layer 3 "l3-No Net 3" (solid, pour order 2): 19.25,80.41
no net on Layer 3 "l3-No Net 4" (solid, pour order 0): 36.71,77.04
no net on Layer 4 "Reference plane to layer L2" (hatched 45Degree grid 0.508 track 0.203, pour order 24): 54.05,37.9 33.437,37.9 33.437,71.908 33.646,72.117 54.05,72.117
no net on Layer0 "Default Coverlay 2 Top" (split plane): 46.651,17.627 46.651,17.45 46.651,6.15 46.658,6.046 46.712,5.844 46.816,5.663 46.964,5.516 47.144,5.411 47.346,5.357 47.555,5.357 47.756,5.411 47.937,5.516 48.085,5.663 48.189,5.844 48.243,6.046 48.25,6.15 48.439,6.1 48.21,4.361 39.304,4.36 39.305,4.905 39.05,4.905 39.05,6.15 39.058,6.046 39.112,5.844 39.216,5.663 39.364,5.516 39.544,5.411 39.746,5.357 39.955,5.357 40.156,5.411 40.337,5.516 40.485,5.663 40.589,5.844 40.643,6.046 40.65,6.15 40.65,17.45 40.65,17.627 40.674,17.75 46.626,17.75
no net on Layer0 "Default Coverlay 2 Top" (split plane): 27.492,87.342 27.674,87.267 27.838,87.157 27.978,87.018 28.087,86.854 28.162,86.672 28.201,86.479 28.201,82.28 28.206,82.182 28.244,81.99 28.319,81.809 28.428,81.646 28.566,81.507 28.729,81.398 28.91,81.323 29.102,81.285 29.2,81.28 29.8,81.28 29.898,81.285 30.091,81.323 30.272,81.398 30.435,81.507 30.573,81.646 30.682,81.809 30.757,81.99 30.795,82.182 30.8,82.28 30.8,83.111 31.78,83.015 31.8,61.416 30.8,61.391 30.8,62.38 30.795,62.478 30.757,62.67 30.682,62.851 30.573,63.014 30.435,63.153 30.272,63.262 30.091,63.337 29.898,63.375 29.8,63.38 29.2,63.38 29.102,63.375 28.91,63.337 28.729,63.262 28.566,63.153 28.428,63.014 28.319,62.851 28.244,62.67 28.206,62.478 28.201,62.38 28.201,58.281 28.162,58.088 28.087,57.906 27.978,57.742 27.838,57.603 27.674,57.493 27.492,57.418 27.299,57.38 27.2,57.38 27.2,87.38 27.299,87.38
no net on Layer0 "Default Coverlay 2 Top" (split plane): 60.1,61.404 59.1,61.379 59.1,62.38 59.095,62.478 59.057,62.67 58.982,62.851 58.873,63.014 58.735,63.153 58.572,63.262 58.391,63.337 58.198,63.375 58.1,63.38 57.5,63.38 57.402,63.375 57.21,63.337 57.029,63.262 56.866,63.153 56.728,63.014 56.619,62.851 56.544,62.67 56.506,62.478 56.501,62.38 56.501,61.498 55.51,61.595 55.51,83.064 56.501,83.162 56.501,82.28 56.506,82.182 56.544,81.99 56.619,81.809 56.728,81.646 56.866,81.507 57.029,81.398 57.21,81.323 57.402,81.285 57.5,81.28 58.1,81.28 58.198,81.285 58.391,81.323 58.572,81.398 58.735,81.507 58.873,81.646 58.982,81.809 59.057,81.99 59.095,82.182 59.1,82.28 59.1,86.38 59.1,86.479 59.138,86.672 59.214,86.854 59.323,87.018 59.463,87.157 59.627,87.267 59.809,87.342 60.002,87.38 60.1,87.38
no net on Layer0 "Default Coverlay 2 Bottom" (split plane): 46.651,17.627 46.651,17.45 46.651,6.15 46.658,6.046 46.712,5.844 46.816,5.663 46.964,5.516 47.144,5.411 47.346,5.357 47.555,5.357 47.756,5.411 47.937,5.516 48.085,5.663 48.189,5.844 48.243,6.046 48.25,6.15 48.439,6.1 48.21,4.361 39.304,4.36 39.305,4.905 39.05,4.905 39.05,6.15 39.058,6.046 39.112,5.844 39.216,5.663 39.364,5.516 39.544,5.411 39.746,5.357 39.955,5.357 40.156,5.411 40.337,5.516 40.485,5.663 40.589,5.844 40.643,6.046 40.65,6.15 40.65,17.45 40.65,17.627 40.674,17.75 46.626,17.75
no net on Layer0 "Default Coverlay 2 Bottom" (split plane): 27.492,87.342 27.674,87.267 27.838,87.157 27.978,87.018 28.087,86.854 28.162,86.672 28.201,86.479 28.201,82.28 28.206,82.182 28.244,81.99 28.319,81.809 28.428,81.646 28.566,81.507 28.729,81.398 28.91,81.323 29.102,81.285 29.2,81.28 29.8,81.28 29.898,81.285 30.091,81.323 30.272,81.398 30.435,81.507 30.573,81.646 30.682,81.809 30.757,81.99 30.795,82.182 30.8,82.28 30.8,83.111 31.78,83.015 31.8,61.416 30.8,61.391 30.8,62.38 30.795,62.478 30.757,62.67 30.682,62.851 30.573,63.014 30.435,63.153 30.272,63.262 30.091,63.337 29.898,63.375 29.8,63.38 29.2,63.38 29.102,63.375 28.91,63.337 28.729,63.262 28.566,63.153 28.428,63.014 28.319,62.851 28.244,62.67 28.206,62.478 28.201,62.38 28.201,58.281 28.162,58.088 28.087,57.906 27.978,57.742 27.838,57.603 27.674,57.493 27.492,57.418 27.299,57.38 27.2,57.38 27.2,87.38 27.299,87.38
no net on Layer0 "Default Coverlay 2 Bottom" (split plane): 60.1,61.404 59.1,61.379 59.1,62.38 59.095,62.478 59.057,62.67 58.982,62.851 58.873,63.014 58.735,63.153 58.572,63.262 58.391,63.337 58.198,63.375 58.1,63.38 57.5,63.38 57.402,63.375 57.21,63.337 57.029,63.262 56.866,63.153 56.728,63.014 56.619,62.851 56.544,62.67 56.506,62.478 56.501,62.38 56.501,61.498 55.51,61.595 55.51,83.064 56.501,83.162 56.501,82.28 56.506,82.182 56.544,81.99 56.619,81.809 56.728,81.646 56.866,81.507 57.029,81.398 57.21,81.323 57.402,81.285 57.5,81.28 58.1,81.28 58.198,81.285 58.391,81.323 58.572,81.398 58.735,81.507 58.873,81.646 58.982,81.809 59.057,81.99 59.095,82.182 59.1,82.28 59.1,86.38 59.1,86.479 59.138,86.672 59.214,86.854 59.323,87.018 59.463,87.157 59.627,87.267 59.809,87.342 60.002,87.38 60.1,87.38
no net on Layer0 "Default Coverlay 4 Bottom" (split plane): 57.601,87.381 57.562,87.188 57.487,87.006 57.378,86.842 57.238,86.703 57.074,86.593 56.892,86.518 56.699,86.48 55.3,86.48 55.222,86.476 55.068,86.445 54.924,86.385 54.793,86.298 54.682,86.187 54.595,86.057 54.535,85.912 54.505,85.758 54.501,85.68 54.501,85.58 54.505,85.502 54.535,85.348 54.595,85.203 54.682,85.073 54.793,84.962 54.924,84.875 55.068,84.815 55.222,84.784 55.3,84.78 55.5,84.78 55.599,84.78 55.792,84.742 55.974,84.667 56.138,84.557 56.278,84.418 56.387,84.254 56.462,84.072 56.501,83.879 56.501,83.78 56.501,82.78 30.8,82.78 30.8,83.879 30.838,84.072 30.914,84.254 31.023,84.418 31.163,84.557 31.327,84.667 31.509,84.742 31.702,84.78 31.8,84.78 32,84.78 32.079,84.784 32.233,84.815 32.377,84.875 32.508,84.962 32.618,85.073 32.706,85.203 32.766,85.348 32.796,85.502 32.8,85.58 32.8,85.68 32.796,85.758 32.766,85.912 32.706,86.057 32.618,86.187 32.508,86.298 32.377,86.385 32.233,86.445 32.079,86.476 32,86.48 30.602,86.48 30.409,86.518 30.227,86.593 30.063,86.703 29.923,86.842 29.814,87.006 29.738,87.188 29.7,87.381 29.7,88.48 57.601,88.48
no net on Layer0 "Default Coverlay 3 Bottom" (split plane): 56.501,60.88 56.501,60.781 56.462,60.588 56.387,60.406 56.278,60.242 56.138,60.103 55.974,59.993 55.792,59.918 55.599,59.88 55.5,59.88 55.3,59.88 55.222,59.876 55.068,59.845 54.924,59.785 54.793,59.698 54.682,59.587 54.595,59.457 54.535,59.312 54.505,59.158 54.501,59.08 54.501,58.98 54.505,58.902 54.535,58.748 54.595,58.603 54.682,58.473 54.793,58.362 54.924,58.275 55.068,58.215 55.222,58.184 55.3,58.18 56.699,58.18 56.892,58.142 57.074,58.067 57.238,57.957 57.378,57.818 57.487,57.654 57.562,57.472 57.601,57.279 57.601,57.18 57.601,55.68 29.7,55.68 29.7,57.18 29.7,57.279 29.738,57.472 29.814,57.654 29.923,57.818 30.063,57.957 30.227,58.067 30.409,58.142 30.602,58.18 32,58.18 32.079,58.184 32.233,58.215 32.377,58.275 32.508,58.362 32.619,58.473 32.706,58.603 32.766,58.748 32.796,58.902 32.8,58.98 32.8,59.08 32.796,59.158 32.766,59.312 32.706,59.457 32.619,59.587 32.508,59.698 32.377,59.785 32.233,59.845 32.079,59.876 32,59.88 31.8,59.88 31.702,59.88 31.509,59.918 31.327,59.993 31.163,60.103 31.023,60.242 30.914,60.406 30.838,60.588 30.8,60.781 30.8,62.38 56.501,62.38
no net on Layer0 "Default Coverlay 5 Top" (split plane): 56.205,34.353 56.129,34.322 55.966,34.213 55.828,34.074 55.719,33.911 55.644,33.73 55.606,33.538 55.601,33.44 55.601,29.44 55.606,29.342 55.644,29.15 55.719,28.969 55.828,28.806 55.966,28.667 56.129,28.558 56.205,28.527 56.104,28.34 31.208,28.358 31.114,28.535 31.172,28.558 31.335,28.667 31.473,28.806 31.582,28.969 31.657,29.15 31.695,29.342 31.7,29.44 31.7,33.44 31.695,33.538 31.657,33.73 31.582,33.911 31.473,34.074 31.335,34.213 31.172,34.322 31.103,34.35 31.201,34.533 56.105,34.54

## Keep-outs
Keep-Out Layer:
  lines w0: 39.046,6.202 39.046,23.049 cw(c39.846,23.049) 39.846,23.849 ; 39.05,6.15 ccw(c39.85,6.15) 40.65,6.15 ; 39.846,23.85 47.442,23.839 cw(c47.442,23.039) 48.242,23.039 ; 40.646,6.202 40.646,21.618 ; 40.646,21.391 cw(c41.287,21.391) 41.287,22.032 46.053,22.032 cw(c46.053,21.439) 46.646,21.439 46.646,6.098 ; 46.65,6.15 ccw(c47.45,6.15) 48.25,6.15 ; 48.246,6.202 48.246,23.039 ; 57.6,92.99 57.6,87.48 cw(c56.6,87.48) 56.6,86.48 55.3,86.48 ccw(c55.3,85.68) 54.5,85.68 54.5,85.58 ccw(c55.3,85.58) 55.3,84.78 55.5,84.78 cw(c55.5,83.78) 56.5,83.78 ; 57.6,104.99 57.6,113.68 ccw(c56.6,113.68) 56.6,114.68 30.7,114.68 ccw(c30.7,113.68) 29.7,113.68 ; 66.79,87.38 60.1,87.38 ccw(c60.1,86.38) 59.1,86.38 59.1,82.28 cw(c58.1,82.28) 58.1,81.28 57.5,81.28 cw(c57.5,82.28) 56.5,82.28 56.5,83.78 ; 66.79,87.39 ccw(c67.8,87.39) 67.8,86.38 75.8,86.38 ccw(c75.8,87.39) 76.81,87.39 ; 76.79,87.38 84.75,87.38 cw(c84.75,86.38) 85.75,86.38 85.75,78.38 ccw(c85.75,77.38) 85.75,76.38 ; 11.49,86.37 cw(c11.49,87.38) 10.48,87.38 2.55,87.38 ccw(c2.55,86.38) 1.55,86.38 1.55,78.38 cw(c1.55,77.38) 1.55,76.38 0,76.38 0,68.38 1.55,68.38 cw(c1.55,67.38) 1.55,66.38 1.55,58.38 ccw(c2.55,58.38) 2.55,57.38 27.2,57.38 ccw(c27.2,58.38) 28.2,58.38 28.2,62.38 cw(c29.2,62.38) 29.2,63.38 29.8,63.38 cw(c29.8,62.38) 30.8,62.38 ; 11.49,86.37 19.49,86.37 ; 11.49,86.37 19.49,86.37 ; 11.49,86.37 19.49,86.37 ; 19.49,86.37 ccw(c19.49,87.38) 20.5,87.38 27.2,87.38 cw(c27.2,86.38) 28.2,86.38 28.2,82.28 ccw(c29.2,82.28) 29.2,81.28 29.8,81.28 ccw(c29.8,82.28) 30.8,82.28 30.8,83.78 cw(c31.8,83.78) 31.8,84.78 32,84.78 ccw(c32,85.58) 32.8,85.58 32.8,85.68 ccw(c32,85.68) 32,86.48 30.7,86.48 cw(c30.7,87.48) 29.7,87.48 ; 28.65,94.99 29.7,94.99 ; 28.65,94.99 29.7,94.99 ; 28.65,94.99 29.7,94.99 ; 28.65,94.99 28.65,102.99 ; 28.65,94.99 28.65,102.99 ; 28.65,94.99 28.65,102.99 ; 28.65,94.99 28.65,102.99 ; 28.65,94.99 28.65,102.99 ; 28.65,94.99 28.65,102.99 ; 28.65,94.99 29.7,94.99 ; 28.65,94.99 29.7,94.99 ; 28.65,94.99 29.7,94.99 ; 28.65,102.99 29.7,102.99 ; 28.65,102.99 29.7,102.99 ; 28.65,102.99 29.7,102.99 ; 28.65,102.99 29.7,102.99 ; 28.65,102.99 29.7,102.99 ; 28.65,102.99 29.7,102.99 ; 29.7,87.48 29.7,92.99 ; 29.7,87.48 29.7,92.99 ; 29.7,92.99 ccw(c29.7,93.99) 29.7,94.99 ; 29.7,92.99 ccw(c29.7,93.99) 29.7,94.99 ; 29.7,92.99 ccw(c29.7,93.99) 29.7,94.99 ; 29.7,92.99 ccw(c29.7,93.99) 29.7,94.99 ; 29.7,92.99 ccw(c29.7,93.99) 29.7,94.99 ; 29.7,92.99 ccw(c29.7,93.99) 29.7,94.99 ; 29.7,102.99 ccw(c29.7,103.99) 29.7,104.99 ; 29.7,102.99 ccw(c29.7,103.99) 29.7,104.99 ; 29.7,102.99 ccw(c29.7,103.99) 29.7,104.99 ; 29.7,102.99 ccw(c29.7,103.99) 29.7,104.99 ; 29.7,102.99 ccw(c29.7,103.99) 29.7,104.99 ; 29.7,102.99 ccw(c29.7,103.99) 29.7,104.99 ; 29.7,104.99 29.7,113.68 ; 29.7,104.99 29.7,113.68 ; 30.8,62.38 30.8,60.88 ccw(c31.8,60.88) 31.8,59.88 32,59.88 cw(c32,59.08) 32.8,59.08 32.8,58.98 cw(c32,58.98) 32,58.18 30.7,58.18 ccw(c30.7,57.18) 29.7,57.18 29.7,35.44 ccw(c30.7,35.44) 30.7,34.44 cw(c30.7,33.44) 31.7,33.44 31.7,29.44 cw(c30.7,29.44) 30.7,28.44 28.9,28.44 ccw(c28.9,27.44) 27.9,27.44 27.9,4.2 ccw(c28.9,4.2) 28.9,3.2 37.3,3.2 cw(c38.3,3.2) 39.3,3.2 39.3,1.35 ccw(c40.65,1.35) 40.65,0 46.65,0 ccw(c46.65,1.35) 48,1.35 48,3.2 cw(c49,3.2) 50,3.2 58.4,3.2 ccw(c58.4,4.2) 59.4,4.2 59.4,27.44 ccw(c58.4,27.44) 58.4,28.44 56.6,28.44 cw(c56.6,29.44) 55.6,29.44 55.6,33.44 cw(c56.6,33.44) 56.6,34.44 ccw(c56.6,35.44) 57.6,35.44 57.6,57.18 ccw(c56.6,57.18) 56.6,58.18 55.3,58.18 cw(c55.3,58.98) 54.5,58.98 54.5,59.08 cw(c55.3,59.08) 55.3,59.88 55.5,59.88 ccw(c55.5,60.88) 56.5,60.88 56.5,62.38 ; 30.8,62.38 30.8,62.38 ; 56.5,62.38 cw(c57.5,62.38) 57.5,63.38 58.1,63.38 cw(c58.1,62.38) 59.1,62.38 59.1,58.38 ccw(c60.1,58.38) 60.1,57.38 84.75,57.38 ccw(c84.75,58.38) 85.75,58.38 85.75,66.38 cw(c85.75,67.38) 85.75,68.38 ; 56.5,62.38 56.5,62.38 ; 56.5,83.78 56.5,83.78 ; 57.61,92.99 cw(c57.61,93.99) 57.61,94.99 ; 57.61,92.99 cw(c57.61,93.99) 57.61,94.99 ; 57.61,92.99 cw(c57.61,93.99) 57.61,94.99 ; 57.61,94.99 58.66,94.99 ; 57.61,94.99 58.66,94.99 ; 57.61,94.99 58.66,94.99 ; 57.61,102.99 cw(c57.61,103.99) 57.61,104.99 ; 57.61,102.99 cw(c57.61,103.99) 57.61,104.99 ; 57.61,102.99 cw(c57.61,103.99) 57.61,104.99 ; 57.61,102.99 58.66,102.99 ; 57.61,102.99 58.66,102.99 ; 57.61,102.99 58.66,102.99 ; 58.66,94.99 58.66,102.99 ; 58.66,94.99 58.66,102.99 ; 58.66,94.99 58.66,102.99 ; 85.75,68.38 87.3,68.38 ; 85.75,68.38 87.3,68.38 ; 85.75,68.38 87.3,68.38 ; 85.75,76.38 87.3,76.38 ; 85.75,76.38 87.3,76.38 ; 85.75,76.38 87.3,76.38 ; 87.3,68.38 87.3,76.38 ; 87.3,68.38 87.3,76.38 ; 87.3,68.38 87.3,76.38 ; 28.575,13.15 ccw(c29.175,13.15) 29.775,13.15 29.775,21.15 ccw(c29.175,21.15) 28.575,21.15 28.575,13.15 ; 39.3,112.805 cw(c39.3,113.405) 39.3,114.005 48,114.005 cw(c48,113.405) 48,112.805 39.3,112.805 ; 40.65,0.75 cw(c40.65,1.35) 40.65,1.95 46.65,1.95 cw(c46.65,1.35) 46.65,0.75 40.65,0.75 ; 57.525,13.15 ccw(c58.125,13.15) 58.725,13.15 58.725,21.15 ccw(c58.125,21.15) 57.525,21.15 57.525,13.15

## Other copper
Top:
  drawing of 28 lines, arcs and shapes, not listed
Layer 2:
  text "layer 2 on flex core  / top side used  / as signal layer" at 65.29,58.23 h2
Layer 3:
  text "layer 3 on flex core  / bottom side used as  / hatch reference layer" at 52.25,68.56 h2
Layer 4:
  text "layer 4 on flex core  / bottom side used as  / hatch reference layer" at 52.24,75.38 h2
Bottom:
  drawing of 33 lines, arcs and shapes, not listed
  text "1F-xRi" at 53.993,100.8 h2
  text "flexible soldermask" at 55.8,98.24 h2
  text "option: lift-off" at 51.452,95.68 h2
  text "xRi-2F-xRi" at 83.75,77.7 h2
  text "ZIF contact & Lift-off" at 23.55,75.457 h2
  text "www.we-online.com/flex" at 53.985,69.32 h2
  text "Hotline:" at 51.404,66.765 h2
  text "flex@we-online.de" at 51.444,64.2 h2
  text "designed by /  / KF, AS & JW /  / 09.05.2019 Rev 2.1" at 20.35,59.62 h1.5
  text "2F-xRi" at 53.993,49.5 h2
  text "flexible soldermask3" at 55.8,47.09 h2
  text "option: lift-off" at 51.452,44.68 h2
  text "Semiflex 1Ri-xRi or 2Ri-xRi" at 55.24,37.82 h2
  text "bending with copper outside only!" at 59.16,25.32 h2

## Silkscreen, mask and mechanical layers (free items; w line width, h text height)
Inner Top Coverlay:
  drawing of 27 lines, arcs and shapes, not listed
Bottom Coverlay:
  drawing of 99 lines, arcs and shapes, not listed
  text "1F-xRi" at 53.993,99.3 h2
  text "flexible soldermask" at 55.8,96.74 h2
  text "option: lift-off" at 51.452,94.18 h2
  text "xRi-2F-xRi" at 83.75,77.7 h2
  text "ZIF contact & Lift-off" at 23.55,75.457 h2
  text "www.we-online.com/flex" at 53.985,69.32 h2
  text "Hotline:" at 51.404,66.765 h2
  text "flex@we-online.de" at 51.444,64.2 h2
  text "designed by /  / KF, AS & JW /  / 09.05.2019 Rev 2.1" at 20.11,59.62 h1.5
  text "2F-xRi" at 53.993,48.5 h2
  text "flexible soldermask" at 55.8,46.59 h2
  text "option: lift-off" at 51.452,44.68 h2
  text "Semiflex 1Ri-xRi or 2Ri-xRi" at 55.2,37.82 h2
  text "bending with copper outside only!" at 59.08,25.32 h2
Board Outline:
  drawing of 227 lines, arcs and shapes, not listed
Rigid Areas:
  drawing of 156 lines, arcs and shapes, not listed
Flexible Areas:
  lines w0: 40.157,5.411 47.144,5.411 cw(c47.45,6.15) 46.65,6.15 ; 40.157,5.411 ccw(c39.85,6.15) 40.65,6.15 ; 40.65,6.15 40.65,16.75 46.65,16.75 46.65,6.046
  lines w0.1: 59.1,82.28 cw(c58.1,82.28) 58.1,81.28 57.5,81.28 cw(c57.5,82.28) 56.5,82.28 56.5,62.38 cw(c57.5,62.38) 57.5,63.38 58.1,63.38 cw(c58.1,62.38) 59.1,62.38 59.1,82.28 ; 59.1,82.28 59.1,82.28 ; 28.2,62.38 cw(c29.2,62.38) 29.2,63.38 29.8,63.38 cw(c29.8,62.38) 30.8,62.38 30.8,82.28 cw(c29.8,82.28) 29.8,81.28 29.2,81.28 cw(c29.2,82.28) 28.2,82.28 28.2,62.38 ; 29.7,56.68 29.7,57.18 cw(c30.7,57.18) 30.7,58.18 32,58.18 ccw(c32,58.98) 32.8,58.98 32.8,59.08 ccw(c32,59.08) 32,59.88 31.8,59.88 cw(c31.8,60.88) 30.8,60.88 30.8,61.38 56.5,61.38 56.5,60.88 cw(c55.5,60.88) 55.5,59.88 55.3,59.88 ccw(c55.3,59.08) 54.5,59.08 54.5,58.98 ccw(c55.3,58.98) 55.3,58.18 56.6,58.18 cw(c56.6,57.18) 57.6,57.18 57.6,56.68 29.7,56.68 ; 29.7,87.48 ccw(c30.7,87.48) 30.7,86.48 32,86.48 cw(c32,85.68) 32.8,85.68 32.8,85.58 cw(c32,85.58) 32,84.78 31.8,84.78 ccw(c31.8,83.78) 30.8,83.78 30.8,83.28 56.5,83.28 56.5,83.78 ccw(c55.5,83.78) 55.5,84.78 55.3,84.78 cw(c55.3,85.58) 54.5,85.58 54.5,85.68 cw(c55.3,85.68) 55.3,86.48 56.6,86.48 ccw(c56.6,87.48) 57.6,87.48 57.6,87.98 29.7,87.98 29.7,87.48 ; 30.7,28.44 ccw(c30.7,29.44) 31.7,29.44 31.7,33.44 ccw(c30.7,33.44) 30.7,34.44 56.6,34.44 ccw(c56.6,33.44) 55.6,33.44 55.6,29.44 ccw(c56.6,29.44) 56.6,28.44 30.7,28.44
  text "1F-xRi mit Lift-Off" at 40.57,85.43 h0.9
  text "xRi-2F-xRi" at 29.84,70.25 h0.9 r90
  text "xRi-2F-xRi" at 58.12,70.12 h0.9 r90
  text "2F-xRi mit Lift-Off" at 40.25,58.84 h0.9
  text "Semiflex" at 42.57,31.08 h0.9
  text "Flexible / Strap /  / xRi-2F-xRi" at 41.7,10.59 h0.9
Help Bending Lines:
  lines w0.2: 29.5,62.38 29.5,63.38 ; 29.5,81.28 29.5,82.28 ; 30.7,31.44 31.7,31.44 ; 31.8,59.03 32.8,59.03 ; 31.8,85.63 32.8,85.63 ; 40.65,7.85 46.65,7.85 ; 40.65,13.7 46.65,13.7 ; 40.65,16.75 46.65,16.75 ; 54.5,59.03 55.5,59.03 ; 54.5,85.63 55.5,85.63 ; 55.6,31.44 56.6,31.44 ; 57.8,62.38 57.8,63.38 ; 57.8,81.28 57.8,82.28
Lasercut:
  lines w0.01: 3.241,70.69 7.941,70.69 3.241,70.69 ; 3.241,70.69 3.241,74.19 ; 3.241,70.69 3.241,74.19 ; 3.241,74.19 7.941,74.19 3.241,74.19 ; 8.141,70.69 9.141,70.69 8.141,70.69 ; 8.141,74.19 9.141,74.19 8.141,74.19 ; 9.341,70.69 10.341,70.69 9.341,70.69 ; 9.341,74.19 10.341,74.19 9.341,74.19 ; 10.541,70.69 11.541,70.69 10.541,70.69 ; 10.541,74.19 11.541,74.19 10.541,74.19 ; 11.741,70.69 12.741,70.69 11.741,70.69 ; 11.741,74.19 12.741,74.19 11.741,74.19 ; 12.941,70.69 13.941,70.69 12.941,70.69 ; 12.941,74.19 13.941,74.19 12.941,74.19 ; 14.141,70.69 15.141,70.69 14.141,70.69 ; 14.141,74.19 15.141,74.19 14.141,74.19 ; 15.341,70.69 16.341,70.69 15.341,70.69 ; 15.341,74.19 16.341,74.19 15.341,74.19 ; 16.541,70.69 17.541,70.69 16.541,70.69 ; 16.541,74.19 17.541,74.19 16.541,74.19 ; 17.741,70.69 18.741,70.69 17.741,70.69 ; 17.741,74.19 18.741,74.19 17.741,74.19 ; 18.941,70.69 19.941,70.69 18.941,70.69 ; 18.941,74.19 19.941,74.19 18.941,74.19 ; 20.141,70.69 21.141,70.69 20.141,70.69 ; 20.141,74.19 21.141,74.19 20.141,74.19 ; 21.341,70.69 22.341,70.69 21.341,70.69 ; 21.341,74.19 22.341,74.19 21.341,74.19 ; 22.541,70.69 23.541,70.69 22.541,70.69 ; 22.541,74.19 23.541,74.19 22.541,74.19 ; 23.741,70.69 24.741,70.69 23.741,70.69 ; 23.741,74.19 24.741,74.19 23.741,74.19 ; 24.941,70.69 25.941,70.69 24.941,70.69 ; 24.941,74.19 25.941,74.19 24.941,74.19
  text "lift-off outline laser cut" at 22.64,71.997 h1.52
DepthMilling:
  rectangle: 40.662,19.21 46.66,22.06
  rectangle: 2.92,70.495 6.82,74.395
  text "ZIF Kontakt, Dicke 0,3mm / gilt für beide ZIF Kontakte" at 23.89,71.11 h1.52
  text "ZIF Kontakt, Dicke 0,3mm / gilt für beide ZIF Kontakte" at 44.95,18.447 h1.52 r90
Drill Drawing:
  rectangle: 6.91,70.145 25.535,74.645
  text "Lift-off area - flex not laminated" at 25.44,75.36 h1.52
